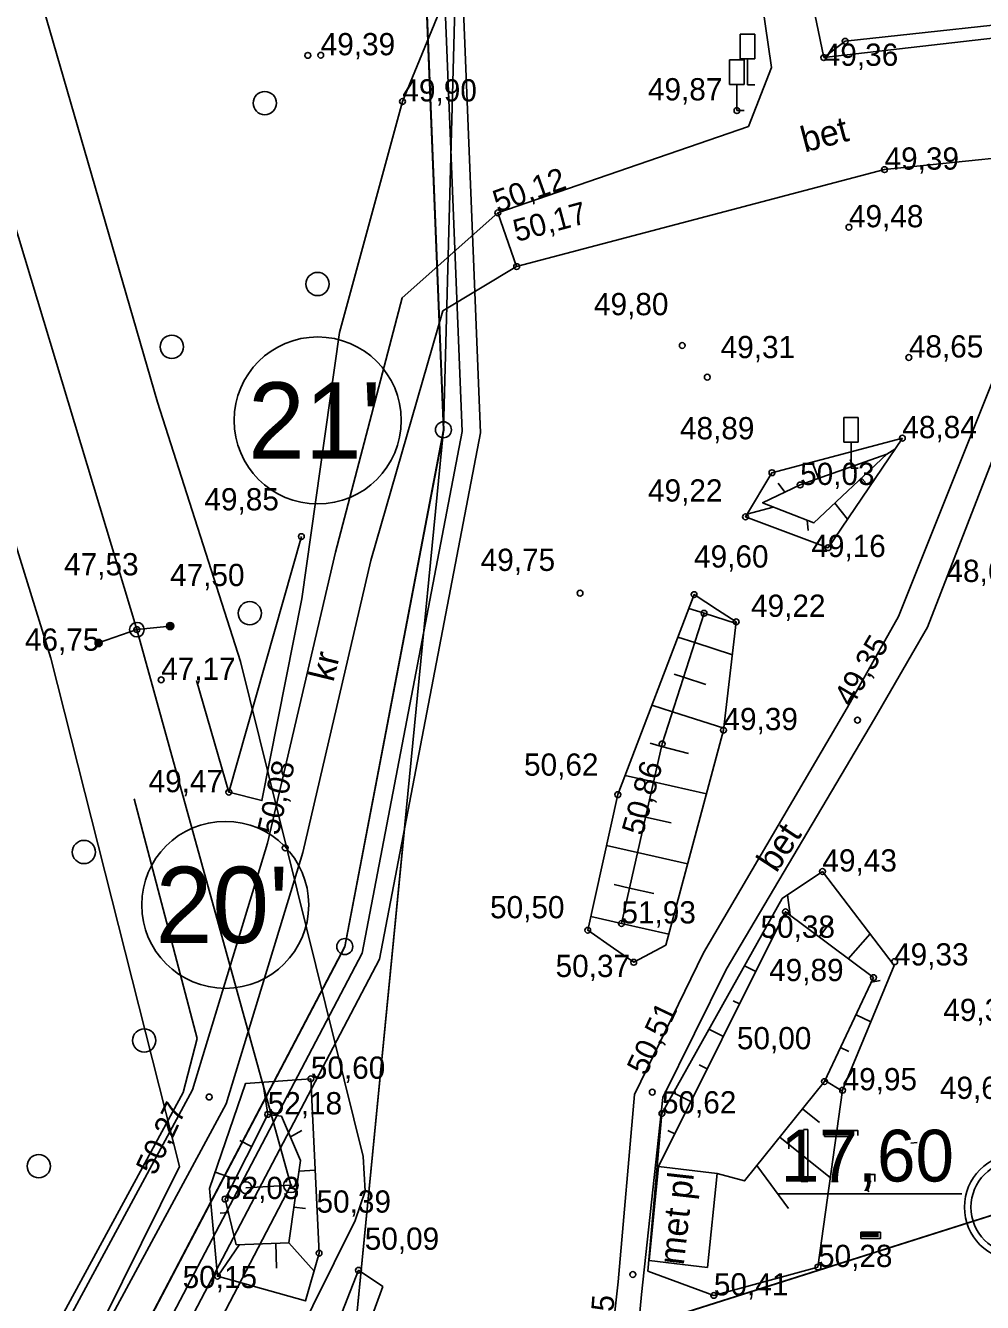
# Model space of a CAD drawing. Extents: x 700746 to 706058, y 6570320 to 6580460.
# Drawn here: x 702807.4 to 702912.8, y 6576171.4 to 6576312 of the extents above; entities that cross this region are included whole.
import ezdxf

# ---------------------------------------------------------------- set-up
doc = ezdxf.new("R2010")
doc.units = 0
for name, color, linetype in [('GEOLPUNKT', 7, 'Continuous'), ('HALJASTUS', 7, 'Continuous'), ('illumineerimisjooned', 7, 'Continuous'), ('Kaitsevöönd', 7, 'Continuous'), ('kataster', 7, 'Continuous'), ('KORGUS-EH2000', 7, 'Continuous'), ('KPKAABEL', 7, 'Continuous'), ('LIIKLUS', 7, 'Continuous'), ('PIIR', 7, 'Continuous'), ('Plokid', 7, 'Continuous'), ('POST', 7, 'Continuous'), ('RAJATIS', 7, 'Continuous'), ('RELJEEF', 7, 'Continuous'), ('TEE', 7, 'Continuous'), ('Tmaad_maeeraldised_kehtivad', 7, 'Continuous'), ('VWX2_MV_PLOKK', 7, 'Continuous')]:
    doc.layers.add(name, color=color, linetype=linetype)

msp = doc.modelspace()

# ---------------------------------------------------------------- linework, layer by layer
at = {"layer": 'GEOLPUNKT'}
msp.add_line((702890.17, 6576183.33), (702910.48, 6576183.33), dxfattribs=at)
msp.add_line((702890.17, 6576183.33), (702910.48, 6576183.33), dxfattribs=at)
for points in [[(702893.07, 6576190.4), (702893.52, 6576190.4), (702893.52, 6576184.68)], [(702895.36, 6576189.63), (702895.36, 6576190.3), (702899.05, 6576190.3), (702899.05, 6576189.76)], [(702891.42, 6576188.29), (702891.42, 6576188.97)], [(702893.52, 6576184.68), (702892.82, 6576184.68), (702892.82, 6576189.13)], [(702898.15, 6576189.63), (702895.36, 6576189.63)], [(702905.58, 6576188.98), (702904.89, 6576188.92)], [(702896.87, 6576184.68), (702896.15, 6576184.68)], [(702900.12, 6576184.68), (702900.12, 6576185.47), (702900.91, 6576185.47), (702900.91, 6576184.68)], [(702900.51, 6576184.68), (702900.12, 6576184.68)], [(702900.26, 6576183.55), (702900.07, 6576183.85)], [(702899.37, 6576178.39), (702899.37, 6576179.09), (702901.52, 6576179.09), (702901.52, 6576178.39), (702899.37, 6576178.39)]]:
    msp.add_lwpolyline(points, dxfattribs=at)
for radius in [5.84, 5.12]:
    msp.add_circle((702916.62, 6576181.85), radius, dxfattribs=at)
at = {"layer": 'HALJASTUS'}
for points in [[(702829.94, 6576500.35), (702842.12, 6576494.02), (702843.27, 6576485.7), (702851.31, 6576459.39), (702860.08, 6576426.66), (702866.16, 6576403.94), (702863.6, 6576397.36), (702866.58, 6576384.71), (702865.59, 6576359.84), (702862.7, 6576338.78), (702855.94, 6576320.86), (702848.88, 6576303.67)], [(702848.88, 6576303.67), (702841.95, 6576278.22), (702837.79, 6576248.86), (702833.41, 6576226.64), (702829.76, 6576227.57), (702826.21, 6576239.88)], [(702819.32, 6576226.85), (702826.28, 6576200.45), (702824.73, 6576194.49), (702810.41, 6576168.09), (702802.1, 6576152.77), (702788.77, 6576128.2), (702779.69, 6576111.46), (702773.4, 6576100.72), (702772.17, 6576091.97), (702771.4, 6576078.33), (702771.76, 6576067.69), (702773.05, 6576060.87), (702783.22, 6576039.64), (702796, 6576024.03), (702793.67, 6576022.36), (702787.01, 6576016.94)]]:
    msp.add_lwpolyline(points, dxfattribs=at)
for centre in [(702833.72, 6576303.49), (702839.53, 6576283.56), (702823.48, 6576276.64), (702832.06, 6576247.29), (702813.8, 6576220.98), (702820.44, 6576200.22), (702808.82, 6576186.37)]:
    msp.add_circle(centre, 1.28, dxfattribs=at)
at = {"layer": 'illumineerimisjooned'}
msp.add_lwpolyline([(703275.45, 6577071.68), (703358.03, 6576531.93), (703309.57, 6576228.79), (703291.69, 6575965.8), (703292.02, 6575933.77), (703296.8, 6575575.06), (702854, 6575511.22), (702839.23, 6575620.77), (702850.34, 6575977.31), (702784.78, 6576064.06), (702784.62, 6576095.83), (702844.43, 6576209.85), (702855.46, 6576267.3), (702846.53, 6576489.41), (702878.89, 6576547.09), (702976.89, 6576643.26), (702915.33, 6577059.56)], dxfattribs=at)
at = {"layer": 'Kaitsevöönd'}
msp.add_lwpolyline([(702820.94, 6576032.47), (702787.75, 6576109.14), (702788.8, 6576114.68), (702824.32, 6576186.32), (702810.14, 6576242.35), (702797.28, 6576283.83), (702800.4, 6576309.17), (702804.69, 6576330.04), (702821.92, 6576270.55), (702831.05, 6576241.98), (702844.55, 6576187.44), (702844.77, 6576183.63), (702843.67, 6576180.38), (702808.74, 6576109.92), (702830.03, 6576060.94)], dxfattribs=at)
at = {"layer": 'kataster'}
msp.add_lwpolyline([(702852.27, 6575508.89), (702837.26, 6575620.73), (702848.38, 6575976.59), (702782.85, 6576063.35), (702782.57, 6576096.37), (702842.53, 6576210.56), (702853.4, 6576267.5), (702844.46, 6576489.93), (702877.29, 6576548.25), (702974.72, 6576643.9), (702913.57, 6577058.07), (702784.04, 6577102.84), (702746.48, 6577248.7), (702719.69, 6577297.36), (702713.81, 6577334.91), (703089.87, 6577211.79), (703231.53, 6577106.55), (703277.36, 6577072.83), (703360.09, 6576531.99), (703311.6, 6576228.52), (703293.62, 6575965.66), (703298.84, 6575573.29)], close=True, dxfattribs=at)
msp.add_lwpolyline([(702628.71, 6576895.25), (702720.42, 6576547.28), (702844.46, 6576489.93), (702853.4, 6576267.5), (702842.53, 6576210.56), (702782.57, 6576096.37), (702782.85, 6576063.35)], dxfattribs=at)
at = {"layer": 'KORGUS-EH2000'}
for centre in [(702897.65, 6576310.3), (702838.46, 6576308.75), (702839.88, 6576308.76), (702895.29, 6576308.5), (702848.88, 6576303.67), (702885.72, 6576302.66), (702901.98, 6576296.16), (702859.38, 6576291.4), (702898.06, 6576289.81), (702861.46, 6576285.48), (702879.7, 6576276.78), (702904.66, 6576275.46), (702882.46, 6576273.29), (702903.94, 6576266.57), (702889.58, 6576262.77), (702892.68, 6576261.42), (702886.66, 6576257.91), (702837.75, 6576255.73), (702895.76, 6576254.51), (702868.44, 6576249.5), (702881, 6576249.34), (702882.1, 6576247.28), (702885.64, 6576246.34), (702819.63, 6576245.48), (702823.29, 6576245.88), (702815.42, 6576244.01), (702822.31, 6576239.95), (702899, 6576235.51), (702884.24, 6576234.41), (702877.48, 6576232.89), (702829.76, 6576227.57), (702872.61, 6576227.3), (702835.97, 6576221.43), (702895.14, 6576218.83), (702891.07, 6576214.4), (702869.29, 6576212.36), (702873, 6576213.11), (702874.35, 6576208.83), (702903.1, 6576208.9), (702900.77, 6576207.14), (702838.79, 6576196), (702895.37, 6576195.69), (702876.4, 6576194.52), (702897.36, 6576194.73), (702827.6, 6576193.99), (702834.04, 6576192.08), (702877.46, 6576192.18), (702829.34, 6576182.75), (702839.7, 6576176.78), (702844.04, 6576174.9), (702874.25, 6576174.43), (702894.65, 6576175.26), (702828.5, 6576174.25), (702883.18, 6576172.13)]:
    msp.add_circle(centre, 0.32, dxfattribs=at)
at = {"layer": 'KPKAABEL'}
for points in [[(702800.4, 6576309.17), (702819.63, 6576245.48)], [(702819.63, 6576245.48), (702836.59, 6576184.26), (702797.6, 6576109.54), (702828.99, 6576046.16), (702858.93, 6575984.92), (702857.42, 6575888.76), (702856.51, 6575810.46), (702856.12, 6575711.01), (702855.37, 6575615.97), (702854.39, 6575550.18), (702865.02, 6575505.16), (702921.92, 6575514.25), (702993.74, 6575525.72), (703056.42, 6575535.34), (703120.25, 6575545.36), (703173.19, 6575553.73), (703215.56, 6575560.47), (703265.05, 6575567.87), (703307.33, 6575597.7), (703332.6, 6575614.36)]]:
    msp.add_lwpolyline(points, dxfattribs=at)
at = {"layer": 'LIIKLUS'}
for p, q in [((702886.08, 6576311.1), (702886.08, 6576308.38)), ((702887.68, 6576311.1), (702886.08, 6576311.1)), ((702887.68, 6576311.1), (702887.68, 6576308.38)), ((702887.68, 6576308.38), (702886.08, 6576308.38)), ((702886.88, 6576308.38), (702886.88, 6576305.5)), ((702884.92, 6576308.26), (702884.92, 6576305.54)), ((702886.52, 6576308.26), (702884.92, 6576308.26)), ((702886.52, 6576308.26), (702886.52, 6576305.54)), ((702886.52, 6576305.54), (702884.92, 6576305.54)), ((702885.72, 6576305.54), (702885.72, 6576302.66)), ((702887.68, 6576305.5), (702886.88, 6576305.5)), ((702886.52, 6576302.66), (702885.72, 6576302.66)), ((702897.49, 6576268.86), (702897.49, 6576266.14)), ((702899.09, 6576268.86), (702897.49, 6576268.86)), ((702899.09, 6576268.86), (702899.09, 6576266.14)), ((702899.09, 6576266.14), (702897.49, 6576266.14)), ((702898.29, 6576266.14), (702898.29, 6576263.26)), ((702899.09, 6576263.26), (702898.29, 6576263.26))]:
    msp.add_line(p, q, dxfattribs=at)
at = {"layer": 'PIIR'}
for centre, radius in [((702839.55, 6576268.53), 9.2), ((702853.4, 6576267.5), 0.88), ((702829.36, 6576215.16), 9.2), ((702842.53, 6576210.56), 0.88)]:
    msp.add_circle(centre, radius, dxfattribs=at)
at = {"layer": 'Plokid'}
msp.add_line((702842.72, 6576158.42), (703067.36, 6576229.67), dxfattribs=at)
for points in [[(702917.13, 6577061.05), (702979.02, 6576642.55), (702880.49, 6576545.86), (702848.55, 6576488.92), (702857.46, 6576267.15), (702846.34, 6576209.18), (702786.62, 6576095.35), (702786.77, 6576064.74), (702852.36, 6575977.95), (702841.24, 6575620.87), (702855.72, 6575513.48), (703019.07, 6575537.04)], [(703072.3, 6576854.63), (703101.31, 6576579.97), (703076.01, 6576303.02), (703067.36, 6576229.67), (703051.03, 6576091.21), (703059.38, 6575886.59), (702981.97, 6575701.33), (702866.03, 6575711.28), (702865.95, 6575985.44), (702842.72, 6576158.42), (702849.09, 6576223.53)]]:
    msp.add_lwpolyline(points, dxfattribs=at)
at = {"layer": 'POST'}
for p, q in [((702815.42, 6576244.01), (702819.63, 6576245.48)), ((702823.29, 6576245.88), (702819.63, 6576245.48)), ((702831.64, 6576184), (702836.59, 6576184.26))]:
    msp.add_line(p, q, dxfattribs=at)
for centre, radius in [((702819.63, 6576245.48), 0.8), ((702819.63, 6576245.48), 0.0747), ((702823.29, 6576245.88), 0.4), ((702823.29, 6576245.88), 0.336), ((702823.29, 6576245.88), 0.272), ((702823.29, 6576245.88), 0.208), ((702823.29, 6576245.88), 0.144), ((702823.29, 6576245.88), 0.0803), ((702823.29, 6576245.88), 0.0163), ((702815.42, 6576244.01), 0.4), ((702815.42, 6576244.01), 0.336), ((702815.42, 6576244.01), 0.272), ((702815.42, 6576244.01), 0.208), ((702815.42, 6576244.01), 0.144), ((702815.42, 6576244.01), 0.0803), ((702815.42, 6576244.01), 0.0163), ((702831.64, 6576184), 0.64), ((702836.59, 6576184.26), 0.8), ((702836.59, 6576184.26), 0.0747)]:
    msp.add_circle(centre, radius, dxfattribs=at)
at = {"layer": 'RAJATIS'}
for p, q in [((702876.05, 6576175.98), (702877.1, 6576186.34)), ((702882.49, 6576175.2), (702876.05, 6576175.98))]:
    msp.add_line(p, q, dxfattribs=at)
msp.add_lwpolyline([(702877.1, 6576186.34), (702883.54, 6576185.57), (702882.49, 6576175.2)], dxfattribs=at)
at = {"layer": 'RELJEEF'}
for p, q in [((702902.24, 6576264.83), (702903.13, 6576265.37)), ((702894.71, 6576262.14), (702894.02, 6576263.94)), ((702898.21, 6576264.24), (702898.48, 6576263.49)), ((702899.87, 6576261.7), (702899.43, 6576262.17)), ((702890.26, 6576261.63), (702891.01, 6576260.63)), ((702896.52, 6576259.42), (702897.89, 6576257.64)), ((702889.73, 6576258.99), (702886.83, 6576258.21)), ((702893.55, 6576256.41), (702893.45, 6576257.53)), ((702882.1, 6576247.28), (702880.42, 6576247.82)), ((702882.1, 6576247.28), (702885.62, 6576246.15)), ((702881.07, 6576244.05), (702879.21, 6576244.65)), ((702881.07, 6576244.05), (702885.22, 6576242.72)), ((702878.81, 6576240.57), (702879.84, 6576240.24)), ((702882.29, 6576239.45), (702879.84, 6576240.24)), ((702878.62, 6576236.43), (702876.36, 6576237.15)), ((702878.62, 6576236.43), (702884.27, 6576234.64)), ((702876.15, 6576232.96), (702877.42, 6576232.62)), ((702880.38, 6576231.82), (702877.42, 6576232.62)), ((702876.53, 6576228.72), (702873.42, 6576229.42)), ((702876.53, 6576228.72), (702882.36, 6576227.4)), ((702873.94, 6576225.2), (702875.65, 6576224.82)), ((702878.49, 6576224.18), (702875.65, 6576224.82)), ((702874.77, 6576220.92), (702871.36, 6576221.69)), ((702874.77, 6576220.92), (702880.28, 6576219.67)), ((702872.19, 6576217.4), (702873.89, 6576217.01)), ((702876.57, 6576216.41), (702873.89, 6576217.01)), ((702891.59, 6576214.01), (702891.29, 6576216.25)), ((702873, 6576213.11), (702869.63, 6576213.88)), ((702873, 6576213.11), (702878.21, 6576211.94)), ((702896.24, 6576213.55), (702894.79, 6576211.62)), ((702889.07, 6576211.72), (702889.58, 6576211.41)), ((702897.99, 6576209.22), (702900.38, 6576211.97)), ((702887.79, 6576207.83), (702886.55, 6576208.44)), ((702901.48, 6576206.82), (702900.54, 6576206.66)), ((702885.3, 6576204.6), (702886.01, 6576204.25)), ((702898.84, 6576203.04), (702900.47, 6576202.27)), ((702884.23, 6576200.66), (702882.64, 6576201.45)), ((702898.04, 6576199), (702897.13, 6576199.43)), ((702881.57, 6576197.52), (702882.44, 6576197.08)), ((702895.42, 6576195.81), (702897.34, 6576194.62)), ((702834.06, 6576192.07), (702833.5, 6576195.63)), ((702880.66, 6576193.5), (702878.74, 6576194.46)), ((702894.8, 6576191.19), (702892.94, 6576192.68)), ((702837.79, 6576190.29), (702836.55, 6576189.59)), ((702878.1, 6576190.31), (702878.88, 6576189.92)), ((702830.96, 6576189.18), (702832.25, 6576188.53)), ((702890.43, 6576189.56), (702896.01, 6576185.07)), ((702877.1, 6576186.34), (702876.95, 6576186.41)), ((702891.4, 6576181.7), (702887.92, 6576186.45)), ((702830.45, 6576184.95), (702828.25, 6576185.71)), ((702837.5, 6576185.83), (702839.26, 6576185.92)), ((702838.2, 6576181.69), (702836.92, 6576181.87)), ((702828.79, 6576181.2), (702829.71, 6576181.26)), ((702830.93, 6576177.73), (702828.54, 6576174.24)), ((702835.02, 6576175.13), (702834.92, 6576177.87)), ((702836.35, 6576177.92), (702839.14, 6576174.8))]:
    msp.add_line(p, q, dxfattribs=at)
for points in [[(702967.2, 6576445.59), (702964.97, 6576430.21), (702957.55, 6576396.12), (702955.71, 6576388.81), (702953.14, 6576387.92), (702952.24, 6576384.17), (702954.89, 6576382.14), (702951.98, 6576371.18), (702943.28, 6576341.71), (702934.94, 6576323.39), (702922.73, 6576313.03), (702897.65, 6576310.3), (702895.29, 6576308.5)], [(702903.94, 6576266.57), (702889.58, 6576262.77), (702886.66, 6576257.91), (702895.76, 6576254.51), (702903.94, 6576266.57)], [(702902.24, 6576264.83), (702892.68, 6576261.42), (702888.55, 6576259.46), (702894.2, 6576257.23), (702902.24, 6576264.83)], [(702837.75, 6576255.73), (702829.76, 6576227.57)], [(702872.13, 6576210.38), (702869.29, 6576212.36), (702872.61, 6576227.3), (702881, 6576249.34), (702883.57, 6576247.68)], [(702873, 6576213.11), (702877.48, 6576232.89), (702882.1, 6576247.28)], [(702883.57, 6576247.68), (702885.64, 6576246.34), (702884.24, 6576234.41), (702877.88, 6576210.72)], [(702894.65, 6576175.26), (702883.18, 6576172.13), (702875.92, 6576174.82), (702877.46, 6576192.18), (702890.69, 6576215.85), (702895.14, 6576218.83), (702903.03, 6576208.48), (702897.36, 6576194.73), (702894.65, 6576175.26)], [(702877.1, 6576186.34), (702891.07, 6576214.4), (702900.77, 6576207.14), (702895.37, 6576195.69), (702886.56, 6576184.75), (702883.54, 6576185.57)], [(702877.88, 6576210.72), (702874.35, 6576208.83), (702872.13, 6576210.38)], [(702838.79, 6576196), (702831.6, 6576195.49), (702827.63, 6576183.9), (702828.5, 6576174.25), (702838.21, 6576171.53), (702839.7, 6576176.78), (702838.79, 6576196)], [(702836.35, 6576177.92), (702837.67, 6576187.01), (702835.55, 6576191.87), (702834.04, 6576192.08), (702829.34, 6576182.75), (702830.58, 6576177.71), (702836.35, 6576177.92)], [(702844.04, 6576174.9), (702840.11, 6576164.86), (702829.43, 6576139.37), (702831.84, 6576125.44), (702834.67, 6576127.13), (702833.44, 6576138.14), (702839.46, 6576153.2), (702846.71, 6576173.11), (702844.04, 6576174.9)]]:
    msp.add_lwpolyline(points, dxfattribs=at)
at = {"layer": 'TEE'}
for points in [[(702928.2, 6576787.25), (702933.99, 6576765.32), (702942.98, 6576731.19), (702949.49, 6576707.92), (702955.65, 6576685.19), (702961.38, 6576663.59), (702967.68, 6576638.65), (702973.34, 6576618.04), (702982.16, 6576576.28), (702985.8, 6576542.79), (702985.29, 6576514.62), (702981.66, 6576479.74), (702977.35, 6576452.44), (702972.82, 6576422.71), (702966.89, 6576396.31), (702959.64, 6576360.66), (702953.49, 6576340.28), (702939.5, 6576315.71), (702926.77, 6576297.4), (702924.1, 6576298.47), (702901.98, 6576296.16)], [(702815.89, 6576615.78), (702823.7, 6576588.22), (702839.83, 6576525.01), (702847.05, 6576498.34), (702868.98, 6576414.36), (702875.79, 6576390.73), (702883.03, 6576363.47), (702888.92, 6576339.34), (702895.29, 6576308.5)], [(702812.05, 6576614.69), (702819.85, 6576587.18), (702835.98, 6576524), (702843.2, 6576497.32), (702865.13, 6576413.3), (702871.95, 6576389.67), (702879.16, 6576362.49), (702885.01, 6576338.58), (702889.54, 6576307.43)], [(702922.52, 6576311.62), (702895.29, 6576308.5)], [(702889.54, 6576307.43), (702886.98, 6576300.92), (702859.38, 6576291.4), (702861.46, 6576285.48), (702901.98, 6576296.16)], [(702865.88, 6576110.72), (702870.06, 6576150.39), (702872.63, 6576173.62), (702874.44, 6576194.27), (702882.04, 6576209.88), (702897.87, 6576236.86), (702903.5, 6576246.94), (702924.1, 6576298.47)], [(702869, 6576109.56), (702873.16, 6576150.16), (702875.2, 6576172.23), (702877.56, 6576193.93), (702884.52, 6576208.02), (702900.89, 6576235.65), (702906.71, 6576245.74), (702926.77, 6576297.4), (702924.1, 6576298.47)], [(702771.81, 6576073.95), (702774.34, 6576099.09), (702780.99, 6576111.89), (702825.75, 6576194.77), (702834.03, 6576221.95), (702841.51, 6576254.02), (702848.86, 6576282.02), (702859.38, 6576291.4)], [(702775.85, 6576074.13), (702778.24, 6576097.93), (702784.53, 6576110.02), (702829.46, 6576193.22), (702837.9, 6576220.91), (702845.41, 6576253.11), (702853.33, 6576280.59), (702861.46, 6576285.48)]]:
    msp.add_lwpolyline(points, dxfattribs=at)
at = {"layer": 'Tmaad_maeeraldised_kehtivad'}
msp.add_lwpolyline([(703277.3, 6577072.8), (703360.06, 6576531.93), (703311.56, 6576228.56), (703293.69, 6575965.74), (703294.02, 6575933.8), (703298.82, 6575573.33), (702852.29, 6575508.95), (702837.23, 6575620.66), (702848.32, 6575976.66), (702782.78, 6576063.39), (702782.61, 6576096.32), (702842.53, 6576210.52), (702853.45, 6576267.45), (702844.51, 6576489.89), (702877.28, 6576548.31), (702974.76, 6576643.97), (702913.53, 6577058.07)], dxfattribs=at)
at = {"layer": 'VWX2_MV_PLOKK'}
for points in [[(702840.26, 6576874.26), (702915.96, 6576894.45), (703039.76, 6576927.49), (703072.13, 6576856.26), (703101.31, 6576579.97), (703076.01, 6576303.02), (703067.36, 6576229.67), (702842.72, 6576158.42), (702853.4, 6576267.5), (702860.12, 6576517.75), (702877.29, 6576548.25), (702900.72, 6576571.25)], [(702840.26, 6576874.26), (702915.96, 6576894.45), (703039.76, 6576927.49), (703072.13, 6576856.26), (703101.31, 6576579.97), (703076.01, 6576303.02), (703067.36, 6576229.67), (702842.72, 6576158.42), (702853.4, 6576267.5), (702860.12, 6576517.75), (702877.29, 6576548.25), (702900.72, 6576571.25)], [(703145.59, 6575981.92), (703053.36, 6575698.14), (703018.17, 6575532.81), (702852.27, 6575508.89), (702837.26, 6575620.73), (702848.38, 6575976.59), (702782.85, 6576063.35), (702782.57, 6576096.37), (702842.53, 6576210.56), (702853.4, 6576267.5), (702842.72, 6576158.42), (702865.95, 6575985.44), (702867.94, 6575888.34), (702866.03, 6575711.28), (702981.97, 6575701.33), (703059.38, 6575886.59), (703051.03, 6576091.21), (703067.36, 6576229.67), (703076.01, 6576303.02), (703101.31, 6576579.97), (703072.3, 6576854.63), (703072.13, 6576856.26), (703120.61, 6576749.6), (703123.04, 6576234.88)], [(703145.59, 6575981.92), (703053.36, 6575698.14), (703018.17, 6575532.81), (702852.27, 6575508.89), (702837.26, 6575620.73), (702848.38, 6575976.59), (702782.85, 6576063.35), (702782.57, 6576096.37), (702842.53, 6576210.56), (702853.4, 6576267.5), (702842.72, 6576158.42), (702865.95, 6575985.44), (702867.94, 6575888.34), (702866.03, 6575711.28), (702981.97, 6575701.33), (703059.38, 6575886.59), (703051.03, 6576091.21), (703067.36, 6576229.67), (703076.01, 6576303.02), (703101.31, 6576579.97), (703072.3, 6576854.63), (703072.13, 6576856.26), (703120.61, 6576749.6), (703123.04, 6576234.88)], [(702860.12, 6576517.75), (702853.4, 6576267.5), (702844.46, 6576489.93)], [(702860.12, 6576517.75), (702853.4, 6576267.5), (702844.46, 6576489.93)]]:
    msp.add_lwpolyline(points, close=True, dxfattribs=at)

# ---------------------------------------------------------------- texts
at = {"layer": 'GEOLPUNKT'}
for s, p in [('17,60', (702890.55, 6576184.68)), ('-', (702899.12, 6576176.68))]:
    msp.add_text(s, height=5.7, dxfattribs=at).set_placement(p)
at = {"layer": 'KORGUS-EH2000'}
for s, p in [('49,39 ', (702839.88, 6576308.76)), ('49,36 ', (702895.29, 6576307.6)), ('49,90 ', (702848.88, 6576303.67)), ('49,87 ', (702875.92, 6576303.79)), ('49,39 ', (702901.98, 6576296.16)), ('49,48 ', (702898.06, 6576289.81)), ('49,80 ', (702869.98, 6576280.12)), ('49,31 ', (702883.93, 6576275.39)), ('48,65 ', (702904.66, 6576275.46)), ('48,89 ', (702879.45, 6576266.45)), ('48,84 ', (702903.94, 6576266.57)), ('50,03 ', (702892.68, 6576261.42)), ('49,22 ', (702875.93, 6576259.59)), ('49,85 ', (702827.07, 6576258.62)), ('49,16 ', (702893.92, 6576253.48)), ('47,53 ', (702811.62, 6576251.46)), ('49,75 ', (702857.5, 6576251.95)), ('49,60 ', (702881, 6576252.32)), ('47,50 ', (702823.29, 6576250.28)), ('48,69 ', (702908.8, 6576250.73)), ('49,22 ', (702887.28, 6576246.89)), ('46,75 ', (702807.3, 6576243.16)), ('47,17 ', (702822.31, 6576239.95)), ('49,39 ', (702884.24, 6576234.41)), ('50,62 ', (702862.27, 6576229.39)), ('49,47 ', (702820.92, 6576227.57)), ('49,43 ', (702895.14, 6576218.83)), ('50,50 ', (702858.53, 6576213.68)), ('51,93 ', (702873, 6576213.11)), ('50,38 ', (702888.32, 6576211.53)), ('49,33 ', (702903.03, 6576208.48)), ('50,37 ', (702865.75, 6576207.21)), ('49,89 ', (702889.27, 6576206.76)), ('49,36 ', (702908.45, 6576202.36)), ('50,00 ', (702885.72, 6576199.25)), ('50,60 ', (702838.79, 6576196)), ('49,95 ', (702897.36, 6576194.73)), ('49,63 ', (702908.08, 6576193.78)), ('52,18 ', (702834.04, 6576192.08)), ('50,62 ', (702877.46, 6576192.18)), ('52,03 ', (702829.34, 6576182.75)), ('50,39 ', (702839.42, 6576181.25)), ('50,09 ', (702844.73, 6576177.16)), ('50,28 ', (702894.65, 6576175.26)), ('50,15 ', (702824.67, 6576172.94)), ('50,41 ', (702883.18, 6576172.13))]:
    msp.add_text(s, height=2.45, dxfattribs=at).set_placement(p)
for s, rotation, p in [('50,12 ', 19.6376, (702859.38, 6576291.4)), ('50,17 ', 15.0864, (702861.46, 6576288.18)), ('49,35 ', 59.4489, (702898.38, 6576236.86)), ('50,08 ', 77.0705, (702835.22, 6576222.73)), ('50,86 ', 74.2418, (702875.34, 6576222.69)), ('50,51 ', 64.6101, (702875.7, 6576196.24)), ('50,27 ', 64.7004, (702821.63, 6576185.24)), ('50,55 ', 85.3902, (702871.59, 6576163.92))]:
    msp.add_text(s, height=2.45, rotation=rotation, dxfattribs=at).set_placement(p)
at = {"layer": 'PIIR'}
for s, p in [("21'", (702831.88, 6576264.33)), ("20'", (702821.7, 6576210.96))]:
    msp.add_text(s, height=8.4, dxfattribs=at).set_placement(p)
at = {"layer": 'TEE'}
for s, rotation, p in [('bet', 14.8756, (702893.19, 6576298.04)), ('kr', 76.3815, (702841.27, 6576239.62)), ('bet', 56.5595, (702890.06, 6576218.59)), ('met pl', 83.595, (702879.86, 6576175.4))]:
    msp.add_text(s, height=2.8, rotation=rotation, dxfattribs=at).set_placement(p)

doc.saveas('drawing.dxf')
